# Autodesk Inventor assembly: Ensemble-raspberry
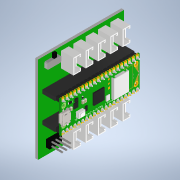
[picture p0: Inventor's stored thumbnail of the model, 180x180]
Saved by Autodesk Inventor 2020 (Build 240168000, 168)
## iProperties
Created: 2023-12
Part Number: Ensemble-raspberry
Document SubType Name: Assembly
Designer: bruno
Author: bruno
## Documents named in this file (3)
- C:\Users\bruno\Downloads\raspberry-pi-pico-w-rp2040-no-pins-pins-and-socketed-1.snapshot.5\Ensemble-raspberry.iam
- C:\Users\bruno\Downloads\raspberry-pi-pico-w-rp2040-no-pins-pins-and-socketed-1.snapshot.5\shield.ipt
- C:\Users\bruno\Downloads\raspberry-pi-pico-w-rp2040-no-pins-pins-and-socketed-1.snapshot.5\RaspberryPi-PicoW-Socketed.ipt
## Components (2 placed, 2 different names)
1. shield:1 — Placage:1, Affleurement:1
2. RaspberryPi-PicoW-Socketed:1 — Placage:1, Affleurement:1
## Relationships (2: Mate 1, Flush 1)
- Placage:1 [Mate]: shield:1 ↔ RaspberryPi-PicoW-Socketed:1
- Affleurement:1 [Flush]: shield:1 ↔ RaspberryPi-PicoW-Socketed:1
